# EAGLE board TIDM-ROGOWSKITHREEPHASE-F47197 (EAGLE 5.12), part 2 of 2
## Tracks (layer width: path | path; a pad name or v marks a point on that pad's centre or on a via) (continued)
N$19 (continued)
  Bottom 0.6: 74,21.3 74,21.36 D22.A | 74,18 D23.C 74.1,17.94 | 74.1,13.3 LSP11.MP
N$20
  Bottom 0.406: 68.2,18 LSP12.MP | 68.2,18.05 68.2,21.48 68.2,24.35 D32.1 | D32.1 | D32.1 R60.2
  Bottom 0.6: 68.2,18 D25.C 68.2,18.05 | LSP12.MP | 68.2,21.5 68.2,21.48 D24.A
N$21
  Bottom 0.406: LSP13.MP 62.4,13.37 D27.C | 62.37,18.03 D26.A 62.4,21.4 62.44,21.44 62.44,24.31 62.4,24.35 D33.2 | D33.2 62.44,24.34 | L17.1 62.19,27.06 62.15,27.1 | L17.1 62.19,24.46 62.2,24.45 D33.2 | 62.2,27 62.19,27.01 L17.1 | D33.2 62.24,27 62.2,27 | 62.2,27 62.19,26.99
  Bottom 0.6: D27.C 62.37,18.03
  Bottom 0.61: 62.4,18.3 arc-90 62.41,18.29 D27.C
N$22
  Bottom 0.406: 56.58,17.88 LSP14.MP | D29.C D28.A 56.61,23.61 57.3,24.3 57.27,24.33 D33.1 57.04,27 57.05,27 56.99,27.04 57,27.05 57.01,27.04 L18.1
  Bottom 0.6: 56.58,17.88 56.62,17.92 D29.C 56.6,18 D29.C
N$23
  Bottom 0.61: R25.2 40.13,30.8 OK4.2
N$24
  Bottom 0.406: R19.2 58.8,30.94 58.8,32.54 R21.1 | R19.2 58.75,30.9 58.67,30.98 54.38,30.98 54.35,30.95 JP19.2 | L18.2 58.1,29 58.75,29.65 58.75,31 58.78,30.97 R19.2
N$25
  Bottom 0.406: 94.1,34.85 94.1,34.75 R11.2 94.14,32.99 C19.1 95.8,32.85 96.2,32.45 96.2,30.95 R7.2 96.5,30.61 R36.1
N$26
  Bottom 0.406: R32.1 79.98,31.1 80,31.1 | R15.1 81.32,33.38 C20.2 80.15,32.9 79.95,32.7 79.95,30.97 R32.1 | R57.1 80.05,30.87 R32.1
N$27
  Bottom 0.406: 68.63,30.97 68.6,31 | R34.1 68.63,30.97 | 68.63,30.97 68.64,30.96 | 69.82,34.73 69.8,34.75 | R18.2 69.82,34.73 | 69.82,34.73 70.1,34.45 70.1,33.2 C50.2 68.8,32.85 68.6,32.65 68.63,32.52 R34.1 | R34.1 68.63,28.87 R60.1
N$28
  Bottom 1.016: D16.A 25.11,221.5 JP7.1
N$29
  Bottom 0.6: 37.71,28.21 37.74,28.24 OK4.3 | T3.C 37.71,28.21 | 37.71,28.21 37.7,28.2
N$30
  Bottom 0.406: T3.B 42.9,29.16 42.9,29.3
  Bottom 0.61: R26.2 42.9,31.02 42.9,29.3
N$31
  Bottom 0.406: R20.1 60.7,32.63 60.7,31.1 60.66,31.1 R19.1 60.5,30.95 60.5,29.7 61.17,29.03 L17.2
N$32
  Bottom 0.406: 100.94,43.36 R53.2 99.08,41.37
  Bottom 0.61: R50.1 100.94,43.36 | 99.09,41.36 99.1,41.35 | 99.09,41.36 R44.2 | 99.08,41.37 99.09,41.36
N$33  (via drill 0.5)
  Top 0.61: v26,30.3 26,35.84 28.86,38.7 30.14,38.7 OK3.2
  Bottom 0.61: D13.C 27.01,40.61 27,40.6 28.88,38.72 OK3.2 | 26,31.53 26,31.6 | 26,31.53 R24.2 | v26,30.3 26,31.53
N$35
  Bottom 1.016: D35.C arc90 85.35,225.13 85.35,226.7 arc90 83.25,228.8 D15.C arc-90 D15.C 82.73,231.22 81.85,232.1 75.05,232.1 JP5.2
N$36
  Bottom 1.016: D15.A | TR1.5 102.23,228.8 D15.A | D34.C 92.85,225.7 92.85,228.75 D15.A
N$37
  Bottom 0.3: 46.08,235.27 46.05,235.3 | 46.08,235.27 R30.2 | 46.14,235.21 46.08,235.27 | 48.75,232.8 48.8,232.7 R31.1 | 48.75,235.01 IC2.4
  Bottom 0.6: IC2.4 46.14,235.21 | 48.75,232.8 48.75,235.01
N$39
  Bottom 1.016: R38.2 R41.1
N$42
  Bottom 0.406: 72.1,34.66 R17.2 72.34,33.04 C50.1 73.65,32.85 73.85,32.65 73.85,30.98 R33.2 | 73.85,30.95 73.83,30.93 R33.2 | 73.83,30.92 73.8,30.95 | R33.2 73.83,30.92 | 73.83,30.92 73.84,30.91 | R58.1 74.05,30.74 R33.2
N$43
  Top 1.016: OK4.5 26.18,25.72 23.9,28 23.9,36.1 23,37 19.2,37 19.1,37.1 X1.5
  Bottom 0.61: C49.- 23.62,37.32 23.36,37.06 | 23.56,40.64 23.5,40.7 | 23.56,40.64 D13.A 23.7,40.73 | 23.56,40.64 23.62,40.58 | OK3.3 29.34,41.26
  Bottom 1: 30.3,41.3 30.26,41.26 OK3.3
  Bottom 1.016: 23.36,37.06 X1.5 | 23.62,40.58 C49.- | 29.34,41.26 27.6,43 24.4,43 23.7,42.3 23.7,40.73
N$45
  Bottom 1.016: R39.2 R42.2
N$46
  Bottom 0.3: U1.96 97.04,62.06 99.4,59.7 110.2,59.7 112.3,61.8 112.3,66.5 115.2,69.4 JTAG.1
N$49
  Bottom 0.61: D12.A 23.38,34.28 23.4,34.3 23.39,34.31 X1.4
N$50
  Bottom 0.61: OK4.8 27.86,33.34 27.75,33.45 | 27.75,33.45 26.9,34.3 26.84,34.24 D12.C 26.76,34.24 26.62,34.38 C49.+ | R22.1 27.15,28.75 27.7,29.3 27.7,33.4 27.75,33.45
N$51
  Bottom 0.406: R45.2 107.35,41.41 107.35,43.15 107.25,43.25 107.29,43.29 R54.2 109.34,43.29 109.35,43.3 109.34,43.31 R51.1
N$52
  Bottom 0.406: 44.7,213.6 44.7,213.54 R43.2 | R40.2 44.7,210.85
  Bottom 1.016: 44.7,210.85 44.7,213.54
N$55
  Bottom 0.3: U1.97 96.54,61.56 99,59.1 110.7,59.1 113,61.4 113,64.7 115.25,66.95 115.3,66.92 115.3,67 JTAG.3
N$56
  Bottom 0.61: X1.2 24.17,28.83 24.2,28.8 | OK4.6 29.26,28.26 27.7,26.7 24.6,26.7 24.2,27.1 24.2,28.8 | 24.2,28.8 24.17,28.77 R22.2
N$57
  Bottom 0.3: R55.2 115.45,43.3 115.43,43.28
  Bottom 0.406: 115.43,43.28 R46.2 | 117.33,43.33 117.35,43.35 | 117.33,43.33 R52.1 | R55.2 117.26,43.26 117.33,43.33
N$60
  Bottom 0.61: R24.1 24,31.5 23.93,31.57 X1.3
N$61
  Bottom 2.54: X1.G2 13.49,44.09 10.5,41.1 10.5,26.4 17.83,19.07 X1.G1
N$62
  Bottom 0.406: R14.1 83.7,34.55 | 85.18,31 85.15,31 | R9.2 85.18,31 | 85.18,31 85.19,31 | 85.2,31 R9.2 | 83.7,34.55 83.7,34.7 | 83.7,34.55 83.7,33.1 C20.1 85.05,32.9 85.35,32.6 85.35,31.14 R9.2 | R56.1 85.3,30.85 R9.2
N$104
  Bottom 0.406: 105.23,96.23 105.25,96.25 | 105.23,96.23 LED1.A | R72.1 104.7,95.7 105.23,96.23
N$105
  Bottom 0.3: LED2.A 105.12,100.78 105.1,100.8 104.7,100.4 104.7,98.58 R73.1
N$107
  Bottom 0.3: LED3.A 105.2,105.5 | LED3.A | R74.1 104.65,103.1 104.65,104.95 LED3.A
N$109  (1 unrouted)
  Bottom 0.61: 42.56,6.39 JP3.1
N$113  (via drill 0.5)
  Top 0.3: v50,23.8 51.15,24.95 v51.15,27.9
  Bottom 0.3: OK2.2 51.32,17.28 50.2,18.4 50.2,23.6 v50,23.8 | R76.2 v51.15,27.9
N$114  (via drill 0.5)  (1 unrouted)
  Top 0.3: v48.25,27.8 48.25,25.05 v45.65,22.45
  Bottom 0.3: R75.2 v48.24,27.81 v48.25,27.8 | v45.65,22.45 45.05,21.85 45.05,15.2
N$116
  Bottom 0.3: U1.98 95.94,61.06 98.5,58.5 111.15,58.5 113.8,61.15 113.8,63 115.3,64.5 JTAG.5
N$117
  Bottom 0.61: OK1.3 45.1,6.4 JP3.2
N$118  (1 unrouted)
  Bottom 0.61: 48.75,6.5 48.81,6.44 JP4.1
N$119  (1 unrouted)
  Bottom 0.61: 51.3,6.45 51.35,6.4 JP4.2
N$120
  Bottom 0.3: T2.B 114.25,107.85 115,107.1 115.4,106.7 115.4,106.2 | 115.4,106.2 115.4,106.15 | R79.2 115.4,106.2
N$121
  Bottom 0.3: R77.1 118.4,118.8 118.38,118.78 | C39.+ 118.27,115.53 118.28,115.52 118.3,115.5
  Bottom 0.6: IRD1.A 118.38,118.78 | R77.1 118.25,118.85 118.28,118.82 118.28,115.52
N$122
  Bottom 0.3: U1.99 95.34,60.56 98,57.9 111.6,57.9 115.35,61.65 115.35,61.9 JTAG.7
N$125
  Bottom 0.3: 114.7,113.8 T1.C 114.65,113.9
  Bottom 0.6: 114.65,113.9 114.04,114.51 IRD1.K
N$126  (2 unrouted)
  Bottom 0.3: R78.2 116.39,102.59 116.75,102.95 116.75,108.35 | 116.75,108.35 116.7,108.4 | T1.B 116.8,110.45 116.8,109 | 116.75,108.35 116.75,108.4 | T2.C 116.65,108.65
N$127
  Bottom 0.61: JTAG.2 117.9,69.55 118.54,70.19 JP1.1
N$129  (1 unrouted)
  Bottom 0.3: 118.2,121.3 118.2,121.43 R82.2
  Bottom 0.6: IC6.3 110.37,118.92 112.75,121.3 | 114.9,121.3 118.2,121.3 | 114.9,121.3 114.93,121.33 C40.+ | R82.2 115.07,121.47 114.9,121.3
  Bottom 0.61: C40.+ 114.97,121.38 114.95,121.4 114.85,121.3 112.75,121.3
N$130  (1 unrouted)
  Bottom 0.61: 117.85,67 119.74,65.11 JP1.3
N$133
  Bottom 1.016: D11.A 68.99,235.7 72.63,235.7 JP10.2
R33
  Bottom 0.3: U1.63 85.03,79.77 82.7,82.1 82.7,83.92 C24.+
REACT  (via drill 0.5, 0.5 pad 0.9)
  Top 0.3: v88.3,100.8 91.6,100.8 92.55,101.75 92.55,102.22 JP15.8 | v79.8,94.5 v75.7,94.5 | v78.95,61.25 78.95,57.05 76.5,54.6 61.35,54.6 60.05,53.3 60.05,45.95 60.2,45.95 v60.25,46.05 | v62.65,107.4 60.65,109.4 53.05,109.4 49.75,112.7 49.75,124.95 arc-90 50.6,125.8 X2.3 52.6,125.75
  Bottom 0.3: v75.7,94.5 75.7,81.8 81.03,76.47 U1.55 81.03,65.13 78.95,63.05 v78.95,61.25 | v79.8,94.5 86.1,100.8 v88.3,100.8 | R76.1 51.14,36.94 v60.25,46.05 | JP15.8 92.53,103.47 91.3,104.7 73.05,104.7 72.35,105.4 70.85,105.4 68.85,107.4 v62.65,107.4
RESET
  Bottom 0.3: U1.100 94.44,60.06 97.2,57.3 108.05,57.3 108.95,56.4 R61.2 C32.1 114.96,56.41 115.36,56.81 JTAG.11 115.36,56.86 115,56.5
RX0  (via drill 0.5, 0.5 pad 0.9)
  Top 0.3: 104.9,108.4 v104.9,108.5 104.9,114.7 IC6.1 | 78.6,115.8 83.6,110.8 83.6,108.65 83.65,108.6 v83.6,108.6 | 78.6,115.8 77.85,116.55 | 77.85,116.55 77.55,116.85 77.7,117 | X3.15 78.87,118.17 78.02,117.32 | 77.85,116.55 78.02,116.38 | 78.02,116.38 78.05,116.35 | 78.02,116.38 77.9,116.5 77.9,117.2 78.02,117.32 | 77.26,117.19 77.89,117.19 77.7,117.18 77.7,117 | 77.25,117.15 77.26,117.19 | 77.26,117.19 77.28,117.17 | 78.6,115.8 77.25,117.15 | 77.25,117.15 69,125.4 69,130.8 68.05,131.75 SV1.6 | 77.7,117 78.02,117.32 | SV1.6 | SV1.6 65.9,131.7 | X2.5 51.17,124.52 arc90 50.6,123.95 50.6,113.3 53.4,110.5 60.85,110.5 62.3,111.95 v64.05,111.95
  Bottom 0.3: 94.06,71.06 arc90 94.7,71.7 | 94.7,71.7 94.7,74.7 95.5,75.5 95.5,82.2 98.9,85.6 98.9,87.6 JP16.6 | 107.9,105.6 105.8,107.7 | 107.9,105.6 107.9,93.5 106.6,92.2 102,92.2 100.21,90.41 100.21,88.91 JP16.6 | 104.9,108.6 v104.9,108.5 | 107.9,105.6 104.9,108.6 | JP16.6 | U1.78 94.06,71.06 | 94.06,71.06 arc90 94.7,71.7 | v83.6,108.6 83.55,108.6 | 104.9,108.6 v83.6,108.6 | v83.6,108.6 79.7,108.6 77.55,110.75 71.4,110.75 70.2,111.95 v64.05,111.95
RX1  (via drill 0.5 pad 0.9)
  Top 0.3: 82.15,49.1 82.2,49.1 | 82.15,49.1 v79.1,49.1 | v86.85,66.9 86.85,66.85 83.85,63.85 83.85,50.25 82.7,49.1 82.15,49.1
  Bottom 0.3: 106.39,80.91 106.4,80.9 | 106.39,80.91 JP14.8 | 106.39,80.91 105.1,82.2 102.8,82.2 99.1,78.5 99.1,73.2 98.3,72.4 98.3,70.6 arc-90 95.76,68.06 95.75,68.05 95.74,68.06 U1.84 | 37.84,41.2 OK3.6 | v79.1,49.1 47.6,49.1 45.35,46.85 | 40.5,41.2 44.45,41.2 45.35,42.1 45.35,46.85 | U1.84 87.91,68.06 86.85,67 v86.85,66.9 | U1.84 95.34,68.06 | 45.35,46.85 45.4,46.9
  Bottom 0.6: R23.2 40.5,41.2 37.84,41.2
SCL  (via drill 0.5)
  Top 0.3: JP16.3 104,87.6 112.5,87.6 v115,85.1
  Bottom 0.3: U1.81 94.96,69.56 arc90 96.5,71.1 96.5,73.5 97.3,74.3 97.3,80.3 102.7,85.7 102.7,86.4 JP16.3 | IC5.6 115.03,86.06 arc90 115,86.1 arc-90 115.01,86.09 R66.1 arc90 115,86.05 v115,85.1
SCLK  (1 unrouted)
  Top 0.3: X2.16 63.93,118.17 69.5,112.6 XL2.4 | XL2.4 69.5,108.9 | XL2.4
  Bottom 0.3: U1.72 89.53,75.63 91.8,77.9 91.8,94 96.35,98.55 96.35,101 97.55,102.2 97.55,103.1 95.25,105.4 73.5,105.4 72.8,106.1 71.3,106.1 69.49,107.91 XL2.4
SDA  (via drill 0.5)
  Top 0.3: JP16.2 113.01,88.89 v113.7,88.2
  Bottom 0.3: JP16.2 104.1,87.7 104.1,85.9 97.9,79.7 97.9,74 97.1,73.2 97.1,71 arc-90 95.16,69.06 U1.82 | 113.77,88.27 IC5.5 | 115.1,88.5 115.07,88.5 R67.1 | R67.1 115.06,88.44 | 113.75,88.25 v113.7,88.2 113.7,88.25 113.75,88.25 | 113.75,88.25 113.77,88.27 | 113.77,88.27 114.2,88.7 R67.1 | 113.75,88.25 113.77,88.25 113.77,88.27 | R67.1 | R67.1 115.2,88.7
SEG0
  Bottom 0.3: U1.19 82.03,54.63 81.1,53.7 | 71.5,51.3 LCD.44 71.5,53.1 72.1,53.7 81.1,53.7 | 81.1,53.7 81.15,53.75
SEG1
  Bottom 0.3: U1.20 81.53,55.33 80.55,54.35 | 80.55,54.35 80.65,54.45 | 80.55,54.35 70.15,54.35 68.9,53.1 68.9,51.4 68.92,51.39 LCD.43
SEG2
  Bottom 0.3: U1.21 81.03,55.83 80.2,55 | 80.2,55 80.25,55.05 | 80.2,55 68.1,55 66.4,53.3 66.4,51.4 LCD.42
SEG3
  Bottom 0.3: U1.22 80.53,56.33 79.9,55.7 | 79.9,55.7 80.5,56.3 | 79.9,55.7 65.8,55.7 63.88,53.78 LCD.41
SEG4
  Bottom 0.3: LCD.40 61.31,51.39 61.3,51.4 61.3,53.35 64.3,56.35 79.55,56.35 80.03,56.83 U1.23
SEG5
  Bottom 0.3: 79.45,57.25 79.2,57 62.5,57 58.8,53.3 LCD.39 | 79.45,57.25 79.5,57.3 | U1.24 79.53,57.33 79.45,57.25
SEG6  (1 unrouted)
  Bottom 0.3: 56.3,51.4 56.27,51.4 LCD.38 56.28,51.39 56.3,51.4 | 56.3,51.4 56.3,52.1 | 56.25,52.1 61.85,57.7 78.9,57.7 79,57.8 79,58.05 79.03,58.08 U1.25
SEG7
  Bottom 0.3: 53.7,51.5 53.7,51.4 LCD.37 53.7,51.41 53.7,51.5 | U1.26 60.26,60.06 53.7,53.5 53.7,51.5
SEG8  (1 unrouted)
  Bottom 0.3: U1.27 57.56,60.56 51.15,54.15 51.15,51.3 | LCD.36 51.2,51.4 LCD.36
SEG9
  Bottom 0.3: U1.28 56.61,61.06 48.6,53.05 48.6,51.35 48.64,51.35 | 48.64,51.35 48.65,51.35 | 48.64,51.35 LCD.35
SEG10
  Bottom 0.3: LCD.34 46.1,51.4 46.1,52 55.66,61.56 U1.29
SEG11
  Bottom 0.3: 43.6,51.4 43.58,51.4 LCD.33 43.59,51.39 43.6,51.4 | U1.30 53.66,62.06 43.6,52 43.6,51.4
SEG12
  Bottom 0.3: U1.31 51.46,62.56 41,52.1 41,51.4 LCD.32
SEG13
  Bottom 0.3: U1.32 49.46,63.06 38.4,52 38.4,51.4 38.41,51.39
  Bottom 0.406: 38.5,51.39 LCD.31 | 38.41,51.39 38.5,51.39 | 38.5,51.39 38.5,51.4
SEG14
  Bottom 0.3: U1.33 47.46,63.56 35.9,52 35.9,51.5 35.94,51.46 LCD.30
SEG15
  Bottom 0.3: U1.34 45.56,64.06 33.5,52 33.4,51.9 LCD.29
SEG16
  Bottom 0.3: U1.35 43.36,64.56 30.9,52.1 30.9,51.4 30.89,51.39 LCD.28
SEG17
  Bottom 0.3: 28.4,51.6 28.4,52.1 41.3,65 | U1.36 41.36,65.06 41.3,65 | LCD.27 28.32,52.02 41.3,65
SEG18
  Bottom 0.3: U1.37 39.16,65.56 25.8,52.2 25.8,51.4 LCD.26
SEG19
  Bottom 0.3: U1.38 37.26,66.06 23.2,52 23.2,51.95 23.2,51.4 23.21,51.39 LCD.25
SEG20
  Bottom 0.3: U1.39 45.74,66.56 23.2,89.1 23.2,99.3 23.4,99.5 23.25,99.65 LCD.24
SEG21
  Bottom 0.3: LCD.23 25.8,99.62 25.8,87.8 | U1.40 46.54,67.06 25.8,87.8 | 25.8,87.8 25.8,87.9
SEG22
  Bottom 0.3: U1.41 47.24,67.56 28.3,86.5 | 28.3,86.5 28.3,86.6 | 28.25,99.65 28.2,99.7 | 28.25,99.65 LCD.22 | 28.3,86.5 28.3,99.6 28.25,99.65
SEG23
  Bottom 0.3: U1.42 47.94,68.06 30.9,85.1 30.9,99.9 30.86,99.86 LCD.21
SEG24
  Bottom 0.3: U1.43 48.54,68.56 33.4,83.7 | 33.4,83.7 33.4,83.8 | 33.4,83.7 LCD.20
SEG25
  Bottom 0.3: U1.44 49.24,69.06 36,82.3 36,99.5 36.15,99.65 | 36.15,99.65 36.2,99.7 | 36.15,99.65 LCD.19
SEG26
  Bottom 0.3: U1.45 50.04,69.56 38.6,81 38.6,99.6 38.55,99.65 LCD.18
SEG27
  Bottom 0.3: U1.46 50.84,70.06 41.1,79.8 41.1,99.25 40.95,99.4 41.02,99.47 LCD.17 41.02,99.28 41.1,99.2
SEG28
  Bottom 0.3: U1.47 51.54,70.56 43.6,78.5 | 43.6,78.5 43.6,78.6 | LCD.16 43.55,99.65 43.5,99.6 43.6,99.5 43.6,78.5
SEG29
  Bottom 0.254: LCD.15 45.72,99.04 46.1,99.04
  Bottom 0.3: U1.48 52.24,71.06 46.1,77.2 46.1,99.04 46.1,99.4 | LCD.15 46.1,99.5
SEG30  (1 unrouted)
  Bottom 0.3: U1.49 53.1,71.56 53.1,71.6 48.7,76 48.7,99.8
SEG31
  Bottom 0.3: U1.50 53.94,72.06 51.2,74.8 51.2,99.6 51.18,99.62 LCD.13
SEG32
  Bottom 0.3: U1.51 79.03,74.37 78.5,74.9 | 53.7,99.66 53.7,99.7 | 53.7,99.66 LCD.12 | 78.5,74.9 79,74.4 | 78.5,74.9 55.7,74.9 53.7,76.9 53.7,99.66
SEG33
  Bottom 0.3: LCD.11 56.3,99.6 56.3,77 57.6,75.7 78.7,75.7 79.53,74.87 U1.52
SEG34
  Bottom 0.3: U1.53 80.03,75.47 79.1,76.4 60,76.4 58.8,77.6 LCD.10
SEG35
  Bottom 0.3: LCD.9 61.3,99.6 LCD.9 | LCD.9 61.4,99.59 61.4,78.7 62.9,77.2 79.4,77.2 80.53,76.07 U1.54
SEG36
  Bottom 0.3: LCD.8 63.88,100.08 63.9,100.05 63.9,101.4 64.4,101.9 88.6,101.9 89.4,101.1 89.4,78.8 87.53,76.93 U1.68
SEG37  (via drill 0.5 pad 0.9)
  Top 0.3: LCD.7 66.42,102.82 v66.5,102.9
  Bottom 0.3: v66.5,102.9 66.8,102.6 89.2,102.6 90,101.8 90,78.6 88.03,76.63 U1.69
SEG38  (via drill 0.5)
  Top 0.3: LCD.6 69,99.7 v69,103.55
  Bottom 0.3: U1.70 88.53,76.33 90.6,78.4 90.6,102.3 89.6,103.3 69.25,103.3 v69,103.55
SEG39  (via drill 0.5 pad 0.9)
  Top 0.3: v71.5,104.3 LCD.5
  Bottom 0.3: v71.5,104.3 71.6,104.3 71.9,104 90.1,104 91.2,102.9 91.2,78.17 89.03,76 U1.71
SI  (via drill 0.5 pad 0.9)  (2 unrouted)
  Top 0.3: 56.3,116.9 X2.18 63.5,116.9 67.5,112.9 67.5,109 67.49,108.99 XL2.3 68.66,107.8 v72.6,107.8
  Bottom 0.3: U1.74 90.53,74.83 93,77.3 93,92.2 98.85,98.05 98.85,100.4 100.1,101.65 100.1,102.2 | 100.15,102.15 100.15,103.55 96.9,106.8 74.6,106.8 73.6,107.8 v72.6,107.8
SO  (via drill 0.5 pad 0.9)  (1 unrouted)
  Top 0.3: X2.20 56.57,115.6 62.9,115.6 66.2,112.3 v66.2,110.65
  Bottom 0.3: U1.73 90.03,75.23 92.4,77.6 92.4,93.4 97.5,98.5 97.5,99.65 | v66.2,110.65 70.15,110.65 71.5,109.3 71.5,109 71.49,108.99 XL2.5 71.49,107.21 71.9,106.8 73.3,106.8 74,106.1 96.2,106.1 98.9,103.4 98.9,101.6 97.61,100.31 JP15.3
TX0  (via drill 0.5, 0.5 pad 0.9)
  Top 0.3: v108.7,106.5 v113.5,106.5 | 59.6,131.75 59.6,131.8 | 59.6,131.75 SV1.1 | 59.6,124.55 59.6,125.05 | 59.6,125.05 59.6,131.75 | X2.7 53.9,123.25 55.2,124.55 56.35,124.55 | 60.1,124.55 66.15,124.55 79.85,110.85 v79.85,110.35 | 60.1,124.55 59.6,124.55 | 59.6,124.55 59.1,124.55 | 59.1,124.55 56.4,124.55 | 59.6,125.05 59.1,124.55 | 60.1,124.55 59.6,125.05
  Top 0.406: 56.35,124.55 56.35,124.54 X2.6 56.4,124.55
  Bottom 0.3: 94.26,70.56 arc90 95.3,71.6 95.3,74.3 96.1,75.1 96.1,81.7 100.2,85.8 100.2,86.4 100.21,86.39 JP16.5 100.2,86.62 100.22,86.64 100.22,86.92 101.5,88.2 101.5,90.3 102.7,91.5 106.9,91.5 108.7,93.3 108.7,93.35 v108.7,106.5 | v108.7,106.5 108.7,106.4 | v108.7,106.5 105.6,109.6 80.6,109.6 | 80.6,109.6 80.9,109.6 | 80.6,109.6 v79.85,110.35 | v113.5,106.5 113.5,105.1 113.6,105 R79.1 | 94.26,70.56 94.24,70.56 | 94.26,70.56 94.29,70.56 | U1.79 94.26,70.56
TX1  (via drill 0.5 pad 0.9)
  Top 0.3: v88.1,66.7 84.6,63.2 84.6,49.75 82.95,48.1 v80.1,48.1
  Bottom 0.254: 80.01,48.1 80.01,48.24 v80.1,48.1
  Bottom 0.3: 103.16,80.96 103.2,80.96 | 103.2,80.96 JP14.7 | 103.2,80.96 103.2,81 103.16,80.96 | 103.16,80.96 103.06,80.96 99.7,77.6 99.7,72.7 98.9,71.9 98.9,70.4 arc-90 96.06,67.56 | 80.2,48.1 v80.1,48.1 80.01,48.1 48.1,48.1 46.1,46.1 | 46.1,46.1 46.15,46.15 | 46.1,46.1 46.1,41.2 42.8,37.9 42.8,33.2 43.1,33.2 42.85,32.95 | 42.85,32.95 42.8,32.9 | 42.85,32.95 R26.1 | v88.1,66.7 88.96,67.56 U1.85 96.14,67.56 96.15,67.55 96.06,67.56 | 96.06,67.56 96.16,67.56
TXE  (via drill 0.5)
  Top 0.3: X2.9 54.03,121.98 55.3,123.25 X2.8 65.75,123.25 66.9,122.1 v66.95,122.1
  Bottom 0.3: U1.80 94.66,70.06 arc90 95.9,71.3 95.9,73.9 96.7,74.7 96.7,80.9 101.5,85.7 101.5,87.1 102.7,88.3 | 102.7,88.3 102.75,88.35 | 102.7,88.3 102.7,88.84 JP16.4 102.75,89.85 103.6,90.7 107.25,90.7 109.7,93.15 109.7,107 106.5,110.2 82.15,110.2 80.7,111.65 71.75,111.65 71,112.4 71,120.45 69.35,122.1 68.8,122.1 v66.95,122.1 67,122.15
V1  (2 unrouted)
  Bottom 0.61: X4.1 101.11,35.51 101.15,35.55 101.15,37.65 R44.1
  Bottom 1.016: X5.1 50.97,223.88 56.8,218.05 56.8,215.29 | 56.8,215.29 56.8,215.2 | R41.2 56.8,215.29
V1+
  Bottom 0.3: 98.95,49.05 98.97,49.05 C41.1 99.05,49.05 99.2,49.05 99.2,50.55 97.1,52.65 91.3,52.65 89.03,54.92 U1.5
  Bottom 0.406: 99.2,49.05 100.35,49.05 101.05,48.35 101.05,47.1 | 101.05,47.05 C13.1 101.05,47.1 | R50.2 101.01,47.06 101.05,47.1
V1-
  Bottom 0.3: C41.2 97.34,49.09 97.35,49.1 97.3,49.15 97.3,50.65 96,51.95 90.85,51.95 88.53,54.27 U1.6
  Bottom 0.406: 95.53,47.13 R47.1 | C14.2 95.52,48.42 96.2,49.1 97.25,49.1 97.26,49.09 C41.2
  Bottom 0.61: C14.2 95.52,47.12 95.53,47.13 95.55,47.15
V2  (1 unrouted)
  Bottom 0.3: 106.19,35.45 106.2,35.45 106.2,35.25
  Bottom 0.6: 106.2,35.5 106.19,35.49 106.19,35.45 X4.3
  Bottom 0.61: R45.1 107.3,39.7 107.3,36.35 106.2,35.25
  Bottom 1.016: X5.3 45.89,224.66 50.65,219.9 R42.1
V2+
  Bottom 0.3: U1.3 90.03,56.12 92.15,54 103.7,54 107.1,50.6 C44.1 107.1,49
  Bottom 0.406: C44.1 107.13,49.02 107.15,49 108.65,49 109.27,48.38 C42.1 109.25,46.9 109.29,46.86 R51.2
V2-
  Bottom 0.3: U1.4 89.53,55.62 91.8,53.35 102.15,53.35 105.4,50.1 C44.2
  Bottom 0.406: C44.2 104.27,49.02 103.65,48.4 C43.2 R48.1
V3  (2 unrouted)
  Bottom 0.3: 111.25,37.1 111.25,37.05
  Bottom 0.61: R46.1 113.83,39.68 111.25,37.1 | X4.5 111.27,34.68 111.25,34.7 111.25,37.05
  Bottom 1.016: X5.5 40.81,225.89 44.7,222 44.7,215.3
V3+
  Bottom 0.3: U1.1 91.03,57.17 92.8,55.4 107.1,55.4 111.3,51.2 114.45,51.2 115.3,50.35 115.3,49
  Bottom 0.406: C47.1 115.3,49 116.2,49 117.35,47.85 117.35,46.9 C45.1 R52.2
V3-
  Bottom 0.3: U1.2 90.53,56.67 92.55,54.65 106.7,54.65 111,50.35 113.1,50.35 113.65,49.8 113.65,48.95 113.6,49 C47.2
  Bottom 0.406: 111.8,47.05 111.8,48.6 112.2,49 C47.2 | C46.2 111.8,47.05 | 111.8,47.05 R49.1
V+  (via drill 0.5 pad 0.9)
  Top 0.3: 79.9,123.2 C38.1
  Top 0.406: 83,123.2 83.03,123.2 X3.7 | 83,122.06 X3.9
  Top 0.6: 83,122.06 83,123.2 80,123.2 arc90 79.9,123.1 C38.1 | v78.4,123.2 79.9,123.2 | v20,72.6 v20,63.3 | v42.7,43.8 v42.7,39.3
  Bottom 0.406: 40.5,36.3 40.4,36.3 40.4,36.92 40.42,36.92 | 39.72,36.08 39.7,36.08 39.7,36.22 39.62,36.22
  Bottom 0.6: 29.71,109 JP18.1 | v20,72.6 20,102.1 26.9,109 28.7,109 | v20,63.3 20,50.7 21.6,49.1 21.65,49.1 | 21.65,49.1 22.5,49.1 | v42.7,39.3 40.5,39.3 | 21.65,49.1 37.4,49.1 v42.7,43.8 | 110.7,125.5 103,125.5 100.7,123.2 v78.4,123.2 61.9,123.2 61.9,123.1 | 110.7,125.5 111,125.5 | 110.7,125.5 112,125.5 113.8,123.7 120.1,123.7 | SV1.2 60.9,131.7 60.9,124.1 | 60.9,123.1 60.9,124.1 | 60.9,110 60.9,109 61.9,109 | 60.9,110 60.9,122.1 | 60.9,122.1 60.9,123.1 | 63.53,109.03 63.6,109 63.5,109 61.9,109 | 60.9,123.1 61.9,123.1 | 60.9,122.1 61.9,123.1 | 61.9,123.1 60.9,124.1 | 28.7,109 30.8,109 | 60.9,110 61.9,109 | 59.9,109 60.9,110 | 30.7,109 29.7,110 28.7,109
  Bottom 0.61: 40.4,33 40.42,33.02 R25.1 40.48,33.02 40.5,33 40.5,36.2 | R23.1 40.5,39.3 40.5,36.3 40.5,36.2 | OK3.8 40.48,36.18 40.5,36.2 | 60.9,109 59.9,109 30.7,109 29.71,109 | XL2.1 63.49,108.99 63.5,109 63.47,109.03 63.53,109.03 | 39.72,36.08 40.42,35.28 | 40.42,36.92 39.62,36.22 | 120.1,123.7 120.2,123.7 121.8,122.1 123.9,122.1 125.45,122.1 126.15,121.4 126.15,118 125.65,117.5 123.5,117.5 JP6.2
VCC  (via drill 0.5, 0.5 pad 0.9, 1 pad 1.78)  (1 unrouted)
  Top 0.406: 35.75,228.1 35.75,228.15
  Top 0.6: v100.05,25.45 v55.25,25.45 | v106.8,96.1 106.8,96.2 106.9,96.1 v114,96.1 117.1,96.1 v118.2,95
  Top 1.016: v28.15,231.6 34.55,231.6 35.65,230.5 35.65,228.2 35.73,228.12 | 35.73,228.12 35.75,228.1 | 35.73,228.12 X5.7
  Bottom 0.254: R30.1 45.54,236.83 45.54,237.11 | 44.27,237.11 44.27,236.83 C6.+
  Bottom 0.3: 106.5,94.2 106.61,94.29 R72.2 106.8,94.4 v106.8,96.1 106.8,98.2 R73.2 | R82.1 120.06,121.5 120.18,121.5 | R74.2 106.45,103 106.5,103 | 128.05,63.6 128.05,63.65
  Bottom 0.406: 115.39,32.05 115.4,32.05 115.3,31.95
  Bottom 0.6: v55.25,25.45 47.85,25.45 | 47.85,25.45 45.5,25.45 42.53,22.48 | 42.53,22.48 42.5,22.45 | 106.8,94.6 v106.8,96.1 106.8,103 106.5,103 | 120.18,121.5 120,121.5 120.08,121.42 R77.2 120.9,117.98 120.9,111.4 | 107.65,25.45 108.8,25.45 115.3,31.95 116.35,31.95 | 107.65,25.45 107.7,25.45 | 107.65,25.45 v100.05,25.45 | 124,31.95 117,31.95 | 117,31.95 116.35,31.95 | v114,96.1 114,96.2 | 124,31.95 123.9,31.95 | 124,31.95 124.95,31.95 125.8,32.8 | 123,58.55 128.05,63.6 | 128.05,63.65 128.05,72.45 125.45,75.05 125.45,80.6 123.2,82.85 120.15,82.85 119,84 119,94.2 v118.2,95 | 106.5,94.2 106.62,94.2 R72.2 | 116.35,31.95 116.35,32.76 | 116.35,32.76 X4.7 | 117,31.95 116.35,32.76 | 115.39,32.05 116.2,32.7 | OK2.1 48.78,15.27 48.8,15.25 48.8,16.9 47.85,17.85 47.85,25.45 | 42.53,22.48 OK1.1
  Bottom 0.61: 125.65,36.55 123.2,39 | 123,58.55 123,39.2 125.65,36.55 | 125.65,36.55 125.75,36.45 | 125.8,32.8 125.8,36.4 125.65,36.55 | v114,96.1 113.95,96.1 113.95,96.8 120.4,103.25 120.4,110.9 120.9,111.4
  Bottom 1.016: IC2.5 45.54,237.11 44.27,237.11 40.26,237.11 40.24,237.09 C7.1 40.24,237.19 | 40.24,237.19 40.25,237.2 | 40.24,237.19 40.05,237 37.6,237 36.8,236.2 36.8,232.6 35.73,231.53 X5.7 | D14.A 27.85,231.61 v28.15,231.6
VREF
  Bottom 0.3: U1.9 87.03,47.67 87.7,47 88.9,47 88.92,46.98 C48.1 89.02,44.22 88.9,44.1 | 88.9,44.1 JP11.1 | 88.9,44.1 88.92,44.12
XIN
  Bottom 0.254: 86.03,79.18 86,79.18 arc90 86,79.17 Q1.2
  Bottom 0.3: U1.65 86.03,79.18 86.03,79.47
XOUT
  Bottom 0.3: 87.3,78.8 87.4,78.9 | 87.3,78.8 87.27,78.83 Q1.1 | 87.3,78.8 86.53,78.03 U1.66
XT2IN
  Bottom 0.3: Q2.2 arc-90 Q2.2 | U1.94 104.04,63.06 arc-90 Q2.2 | C21.1 107.61,62.51 arc-90 107.6,62.5 arc-90 107.5,62.4 Q2.2
XT2OUT
  Bottom 0.3: C22.1 107.6,68.75 107.55,68.8 105.8,68.8 arc90 104.69,67.69 Q2.1 Q2.1 arc90 104.7,67.2 arc-90 101.06,63.56 U1.93
(copper drawn outside any net)
  shapes: Bottom circle x4

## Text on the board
bPlace: VCC | DVCC
tNames: LSD-ET471X7-01A_V5.0
bNames: LSD-ET471X7-01B_V5.0 | V3 | V2 | V1 | CA1 | CA0 | VCC | GND | GND | GND | DVCC | V1 | GND | V2 | GND | V3 | GND | CA0 | CA1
